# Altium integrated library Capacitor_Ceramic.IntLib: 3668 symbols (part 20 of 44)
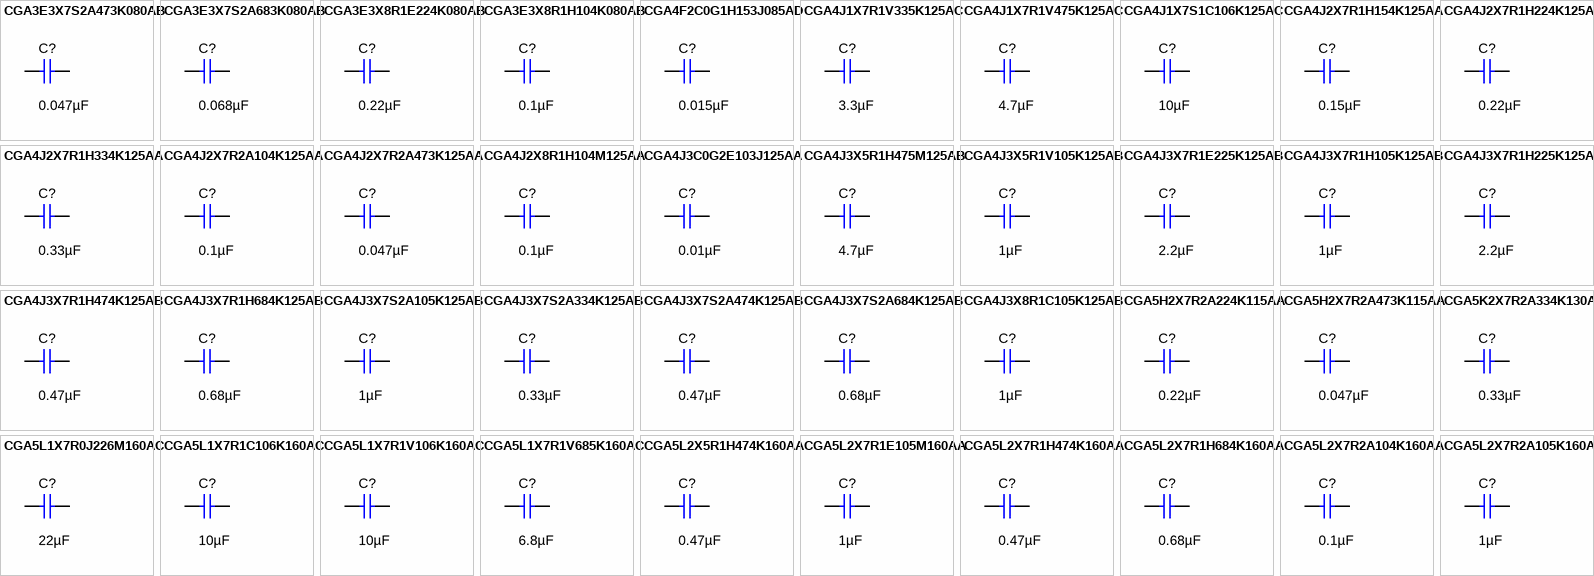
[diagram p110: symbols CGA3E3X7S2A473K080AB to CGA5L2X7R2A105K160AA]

## CGA4J2X7R2A104K125AA
designator C?  ValueDisplayed: 0.1µF  (hidden comment: CGA4J2X7R2A104K125AA)
CAP, CERM, 0.1 µF, 100 V,+/- 10%, X7R, AEC-Q200 Grade 1, 0805; Manufacturer: TDK; Polarized: N; CompType: Capacitor; Value: 0.1uF; U/M: EA; Cap_F: 0.0000001; Tolerance_%: 10; ESR_ohm: 0.020726; Value1: 0.020726 ohm; VDC_V: 100; Value2: 100V; IRMS_A: 1.456; TaMin_C: -55; TaMax_C: 125; Cap_Case: 0805; SizeArea_mm2: 2.5; SizeAreaWB_mm2: 6.75; SizeX_mm: 2; SizeY_mm: 1.25; SizeZ_mm: 1.45; AEC Category: Q200; AEC Qualified: Y; AEC Grade: 1; Green_Lifecycle: Active; Green_REACh: Passed
signal-integrity model Cap
simulation model Cap
footprint 0805_HV
footprint 0805_HV1
footprint 0805
footprint 0805M
footprint 0805L
pins: 1, 2

## CGA4J2X7R2A473K125AA
designator C?  ValueDisplayed: 0.047µF  (hidden comment: CGA4J2X7R2A473K125AA)
CAP, CERM, 0.047 µF, 100 V,+/- 10%, X7R, AEC-Q200 Grade 1, 0805; Manufacturer: TDK; Polarized: N; CompType: Capacitor; Value: 0.047uF; U/M: EA; Cap_F: 0.000000047; Tolerance_%: 10; ESR_ohm: 0.049089; Value1: 0.049089 ohm; VDC_V: 100; Value2: 100V; IRMS_A: 0.963171; TaMin_C: -55; TaMax_C: 125; Cap_Case: 0805; SizeArea_mm2: 2.5; SizeAreaWB_mm2: 6.75; SizeX_mm: 2; SizeY_mm: 1.25; SizeZ_mm: 1.45; AEC Category: Q200; AEC Qualified: Y; AEC Grade: 1
signal-integrity model Cap
simulation model Cap
footprint 0805_HV
footprint 0805_HV1
footprint 0805
footprint 0805M
footprint 0805L
pins: 1, 2

## CGA4J2X8R1H104M125AA
designator C?  ValueDisplayed: 0.1µF  (hidden comment: CGA4J2X8R1H104M125AA)
CAP, CERM, 0.1 µF, 50 V,+/- 20%, X8R, AEC-Q200 Grade 0, 0805; Manufacturer: TDK; Polarized: N; CompType: Capacitor; Value: 0.1uF; U/M: EA; Cap_F: 0.0000001; Tolerance_%: 20; VDC_V: 50; Value2: 50V; TaMin_C: -55; TaMax_C: 150; Cap_Case: 0805; SizeArea_mm2: 2.5; SizeAreaWB_mm2: 6.75; SizeX_mm: 2; SizeY_mm: 1.25; SizeZ_mm: 1.45; AEC Category: Q200; AEC Qualified: Y; AEC Grade: 0
signal-integrity model Cap
simulation model Cap
footprint 0805_HV
footprint 0805_HV1
footprint 0805
footprint 0805M
footprint 0805L
pins: 1, 2

## CGA4J3C0G2E103J125AA
designator C?  ValueDisplayed: 0.01µF  (hidden comment: CGA4J3C0G2E103J125AA)
CAP, CERM, 0.01 µF, 250 V,+/- 5%, C0G/NP0, AEC-Q200 Grade 1, 0805; Manufacturer: TDK; Polarized: N; CompType: Capacitor; Value: 0.01uF; U/M: EA; Cap_F: 0.00000001; Tolerance_%: 5; VDC_V: 250; Value2: 250V; TaMin_C: -55; TaMax_C: 125; Cap_Case: 0805; SizeArea_mm2: 2.5; SizeAreaWB_mm2: 6.75; SizeX_mm: 2; SizeY_mm: 1.25; SizeZ_mm: 1.45; AEC Category: Q200; AEC Qualified: Y; AEC Grade: 1; Green_Lifecycle: Active; Green_REACh: Passed
signal-integrity model Cap
simulation model Cap
footprint 0805_HV
footprint 0805_HV1
footprint 0805
footprint 0805M
footprint 0805L
pins: 1, 2

## CGA4J3X5R1H475M125AB
designator C?  ValueDisplayed: 4.7µF  (hidden comment: CGA4J3X5R1H475M125AB)
CAP, CERM, 4.7 µF, 50 V,+/- 20%, X5R, AEC-Q200 Grade 3, 0805; Manufacturer: TDK; Polarized: N; CompType: Capacitor; Value: 4.7uF; U/M: EA; Cap_F: 0.0000047; Tolerance_%: 20; VDC_V: 50; Value2: 50V; TaMin_C: -55; TaMax_C: 85; Cap_Case: 0805; SizeArea_mm2: 2.5; SizeAreaWB_mm2: 6.75; SizeX_mm: 2; SizeY_mm: 1.25; SizeZ_mm: 1.45; AEC Category: Q200; AEC Qualified: Y; AEC Grade: 3
signal-integrity model Cap
simulation model Cap
footprint 0805_HV
footprint 0805_HV1
footprint 0805
footprint 0805M
footprint 0805L
pins: 1, 2

## CGA4J3X5R1V105K125AB
designator C?  ValueDisplayed: 1µF  (hidden comment: CGA4J3X5R1V105K125AB)
CAP, CERM, 1 µF, 35 V,+/- 10%, X5R, AEC-Q200 Grade 3, 0805; Manufacturer: TDK; Polarized: N; CompType: Capacitor; Value: 1uF; U/M: EA; Cap_F: 0.000001; Tolerance_%: 10; VDC_V: 35; Value2: 35V; TaMin_C: -55; TaMax_C: 85; Cap_Case: 0805; SizeArea_mm2: 2.5; SizeAreaWB_mm2: 6.75; SizeX_mm: 2; SizeY_mm: 1.25; SizeZ_mm: 1.45; AEC Category: Q200; AEC Qualified: Y; AEC Grade: 3
signal-integrity model Cap
simulation model Cap
footprint 0805_HV
footprint 0805_HV1
footprint 0805
footprint 0805M
footprint 0805L
pins: 1, 2

## CGA4J3X7R1E225K125AB
designator C?  ValueDisplayed: 2.2µF  (hidden comment: CGA4J3X7R1E225K125AB)
CAP, CERM, 2.2 µF, 25 V,+/- 10%, X7R, AEC-Q200 Grade 1, 0805; Manufacturer: TDK; Polarized: N; CompType: Capacitor; Value: 2.2uF; U/M: EA; Cap_F: 0.0000022; Tolerance_%: 10; VDC_V: 25; Value2: 25V; TaMin_C: -55; TaMax_C: 125; Cap_Case: 0805; SizeArea_mm2: 2.5; SizeAreaWB_mm2: 6.75; SizeX_mm: 2; SizeY_mm: 1.25; SizeZ_mm: 1.45; AEC Category: Q200; AEC Qualified: Y; AEC Grade: 1; Green_Lifecycle: Active; Green_REACh: Passed
signal-integrity model Cap
simulation model Cap
footprint 0805_HV
footprint 0805_HV1
footprint 0805
footprint 0805M
footprint 0805L
pins: 1, 2

## CGA4J3X7R1H105K125AB
designator C?  ValueDisplayed: 1µF  (hidden comment: CGA4J3X7R1H105K125AB)
CAP, CERM, 1 µF, 50 V,+/- 10%, X7R, AEC-Q200 Grade 1, 0805; Manufacturer: TDK; Polarized: N; CompType: Capacitor; Value: 1uF; U/M: EA; Cap_F: 0.000001; Tolerance_%: 10; ESR_ohm: 0.008782; Value1: 0.008782 ohm; VDC_V: 50; Value2: 50V; IRMS_A: 2.20488; TaMin_C: -55; TaMax_C: 125; Cap_Case: 0805; SizeArea_mm2: 2.5; SizeAreaWB_mm2: 6.75; SizeX_mm: 2; SizeY_mm: 1.25; SizeZ_mm: 1.45; AEC Category: Q200; AEC Qualified: Y; AEC Grade: 1
signal-integrity model Cap
simulation model Cap
footprint 0805_HV
footprint 0805_HV1
footprint 0805
footprint 0805M
footprint 0805L
pins: 1, 2

## CGA4J3X7R1H225K125AB
designator C?  ValueDisplayed: 2.2µF  (hidden comment: CGA4J3X7R1H225K125AB)
CAP, CERM, 2.2 µF, 50 V,+/- 10%, X7R, AEC-Q200 Grade 1, 0805; Manufacturer: TDK; Polarized: N; CompType: Capacitor; Value: 2.2uF; U/M: EA; Cap_F: 0.0000022; Tolerance_%: 10; ESR_ohm: 0.003288; Value1: 0.003288 ohm; VDC_V: 50; Value2: 50V; IRMS_A: 3.60029; TaMin_C: -55; TaMax_C: 125; Cap_Case: 0805; SizeArea_mm2: 2.5; SizeAreaWB_mm2: 6.75; SizeX_mm: 2; SizeY_mm: 1.25; SizeZ_mm: 1.45; AEC Category: Q200; AEC Qualified: Y; AEC Grade: 1
signal-integrity model Cap
simulation model Cap
footprint 0805_HV
footprint 0805_HV1
footprint 0805
footprint 0805M
footprint 0805L
pins: 1, 2

## CGA4J3X7R1H474K125AB
designator C?  ValueDisplayed: 0.47µF  (hidden comment: CGA4J3X7R1H474K125AB)
CAP, CERM, 0.47 µF, 50 V,+/- 10%, X7R, AEC-Q200 Grade 1, 0805; Manufacturer: TDK; Polarized: N; CompType: Capacitor; Value: 0.47uF; U/M: EA; Cap_F: 0.00000047; Tolerance_%: 10; ESR_ohm: 0.022012; Value1: 0.022012 ohm; VDC_V: 50; Value2: 50V; IRMS_A: 1.39566; TaMin_C: -55; TaMax_C: 125; Cap_Case: 0805; SizeArea_mm2: 2.5; SizeAreaWB_mm2: 6.75; SizeX_mm: 2; SizeY_mm: 1.25; SizeZ_mm: 1.45; AEC Category: Q200; AEC Qualified: Y; AEC Grade: 1
signal-integrity model Cap
simulation model Cap
footprint 0805_HV
footprint 0805_HV1
footprint 0805
footprint 0805M
footprint 0805L
pins: 1, 2

## CGA4J3X7R1H684K125AB
designator C?  ValueDisplayed: 0.68µF  (hidden comment: CGA4J3X7R1H684K125AB)
CAP, CERM, 0.68 µF, 50 V,+/- 10%, X7R, AEC-Q200 Grade 1, 0805; Manufacturer: TDK; Polarized: N; CompType: Capacitor; Value: 0.68uF; U/M: EA; Cap_F: 0.00000068; Tolerance_%: 10; ESR_ohm: 0.011711; Value1: 0.011711 ohm; VDC_V: 50; Value2: 50V; IRMS_A: 1.91098; TaMin_C: -55; TaMax_C: 125; Cap_Case: 0805; SizeArea_mm2: 2.5; SizeAreaWB_mm2: 6.75; SizeX_mm: 2; SizeY_mm: 1.25; SizeZ_mm: 1.45; AEC Category: Q200; AEC Qualified: Y; AEC Grade: 1
signal-integrity model Cap
simulation model Cap
footprint 0805_HV
footprint 0805_HV1
footprint 0805
footprint 0805M
footprint 0805L
pins: 1, 2

## CGA4J3X7S2A105K125AB
designator C?  ValueDisplayed: 1µF  (hidden comment: CGA4J3X7S2A105K125AB)
CAP, CERM, 1 µF, 100 V,+/- 10%, X7S, AEC-Q200 Grade 1, 0805; Manufacturer: TDK; Polarized: N; CompType: Capacitor; Value: 1uF; U/M: EA; Cap_F: 0.000001; Tolerance_%: 10; ESR_ohm: 0.008255; Value1: 0.008255 ohm; VDC_V: 100; Value2: 100V; IRMS_A: 2.27442; TaMin_C: -55; TaMax_C: 125; Cap_Case: 0805; SizeArea_mm2: 2.5; SizeAreaWB_mm2: 6.75; SizeX_mm: 2; SizeY_mm: 1.25; SizeZ_mm: 1.45; AEC Category: Q200; AEC Qualified: Y; AEC Grade: 1
signal-integrity model Cap
simulation model Cap
footprint 0805_HV
footprint 0805_HV1
footprint 0805
footprint 0805M
footprint 0805L
pins: 1, 2

## CGA4J3X7S2A334K125AB
designator C?  ValueDisplayed: 0.33µF  (hidden comment: CGA4J3X7S2A334K125AB)
CAP, CERM, 0.33 µF, 100 V,+/- 10%, X7S, AEC-Q200 Grade 1, 0805; Manufacturer: TDK; Polarized: N; CompType: Capacitor; Value: 0.33uF; U/M: EA; Cap_F: 0.00000033; Tolerance_%: 10; ESR_ohm: 0.019477; Value1: 0.019477 ohm; VDC_V: 100; Value2: 100V; IRMS_A: 1.48561; TaMin_C: -55; TaMax_C: 125; Cap_Case: 0805; SizeArea_mm2: 2.5; SizeAreaWB_mm2: 6.75; SizeX_mm: 2; SizeY_mm: 1.25; SizeZ_mm: 1.45; AEC Category: Q200; AEC Qualified: Y; AEC Grade: 1
signal-integrity model Cap
simulation model Cap
footprint 0805_HV
footprint 0805_HV1
footprint 0805
footprint 0805M
footprint 0805L
pins: 1, 2

## CGA4J3X7S2A474K125AB
designator C?  ValueDisplayed: 0.47µF  (hidden comment: CGA4J3X7S2A474K125AB)
CAP, CERM, 0.47 µF, 100 V,+/- 10%, X7S, AEC-Q200 Grade 1, 0805; Manufacturer: TDK; Polarized: N; CompType: Capacitor; Value: 0.47uF; U/M: EA; Cap_F: 0.00000047; Tolerance_%: 10; ESR_ohm: 0.017152; Value1: 0.017152 ohm; VDC_V: 100; Value2: 100V; IRMS_A: 1.58068; TaMin_C: -55; TaMax_C: 125; Cap_Case: 0805; SizeArea_mm2: 2.5; SizeAreaWB_mm2: 6.75; SizeX_mm: 2; SizeY_mm: 1.25; SizeZ_mm: 1.45; AEC Category: Q200; AEC Qualified: Y; AEC Grade: 1
signal-integrity model Cap
simulation model Cap
footprint 0805_HV
footprint 0805_HV1
footprint 0805
footprint 0805M
footprint 0805L
pins: 1, 2

## CGA4J3X7S2A684K125AB
designator C?  ValueDisplayed: 0.68µF  (hidden comment: CGA4J3X7S2A684K125AB)
CAP, CERM, 0.68 µF, 100 V,+/- 10%, X7S, AEC-Q200 Grade 1, 0805; Manufacturer: TDK; Polarized: N; CompType: Capacitor; Value: 0.68uF; U/M: EA; Cap_F: 0.00000068; Tolerance_%: 10; ESR_ohm: 0.009732; Value1: 0.009732 ohm; VDC_V: 100; Value2: 100V; IRMS_A: 2.09614; TaMin_C: -55; TaMax_C: 125; Cap_Case: 0805; SizeArea_mm2: 2.5; SizeAreaWB_mm2: 6.75; SizeX_mm: 2; SizeY_mm: 1.25; SizeZ_mm: 1.45; AEC Category: Q200; AEC Qualified: Y; AEC Grade: 1
signal-integrity model Cap
simulation model Cap
footprint 0805_HV
footprint 0805_HV1
footprint 0805
footprint 0805M
footprint 0805L
pins: 1, 2

## CGA4J3X8R1C105K125AB
designator C?  ValueDisplayed: 1µF  (hidden comment: CGA4J3X8R1C105K125AB)
CAP, CERM, 1 µF, 16 V,+/- 20%, X8R, AEC-Q200 Grade 0, 0805; Manufacturer: TDK; Polarized: N; CompType: Capacitor; Value: 1uF; U/M: EA; Cap_F: 0.000001; Tolerance_%: 20; VDC_V: 16; Value2: 16V; TaMin_C: -55; TaMax_C: 150; Cap_Case: 0805; SizeArea_mm2: 2.5; SizeAreaWB_mm2: 6.75; SizeX_mm: 2; SizeY_mm: 1.25; SizeZ_mm: 1.45; AEC Category: Q200; AEC Qualified: Y; AEC Grade: 0
signal-integrity model Cap
simulation model Cap
footprint 0805_HV
footprint 0805_HV1
footprint 0805
footprint 0805M
footprint 0805L
pins: 1, 2

## CGA5H2X7R2A224K115AA
designator C?  ValueDisplayed: 0.22µF  (hidden comment: CGA5H2X7R2A224K115AA)
CAP, CERM, 0.22 µF, 100 V,+/- 10%, X7R, AEC-Q200 Grade 1, 1206; Manufacturer: TDK; Polarized: N; CompType: Capacitor; Value: 0.22uF; U/M: EA; Cap_F: 0.00000022; Tolerance_%: 10; ESR_ohm: 0.01493; Value1: 0.01493 ohm; VDC_V: 100; Value2: 100V; IRMS_A: 1.89056; TaMin_C: -55; TaMax_C: 125; Cap_Case: 1206; SizeArea_mm2: 5.12; SizeAreaWB_mm2: 10.92; SizeX_mm: 3.2; SizeY_mm: 1.6; SizeZ_mm: 1.35; AEC Category: Q200; AEC Qualified: Y; AEC Grade: 1
signal-integrity model Cap
simulation model Cap
footprint 1206
footprint 1206M
footprint 1206L
pins: 1, 2

## CGA5H2X7R2A473K115AA
designator C?  ValueDisplayed: 0.047µF  (hidden comment: CGA5H2X7R2A473K115AA)
CAP, CERM, 0.047 µF, 100 V,+/- 10%, X7R, AEC-Q200 Grade 1, 1206; Manufacturer: TDK; Polarized: N; CompType: Capacitor; Value: 0.047uF; U/M: EA; Cap_F: 0.000000047; Tolerance_%: 10; ESR_ohm: 0.065629; Value1: 0.065629 ohm; VDC_V: 100; Value2: 100V; IRMS_A: 0.927421; TaMin_C: -55; TaMax_C: 125; Cap_Case: 1206; SizeArea_mm2: 5.12; SizeAreaWB_mm2: 10.92; SizeX_mm: 3.2; SizeY_mm: 1.6; SizeZ_mm: 1.35; AEC Category: Q200; AEC Qualified: Y; AEC Grade: 1
signal-integrity model Cap
simulation model Cap
footprint 1206
footprint 1206M
footprint 1206L
pins: 1, 2

## CGA5K2X7R2A334K130AA
designator C?  ValueDisplayed: 0.33µF  (hidden comment: CGA5K2X7R2A334K130AA)
CAP, CERM, 0.33 µF, 100 V,+/- 10%, X7R, AEC-Q200 Grade 1, 1206; Manufacturer: TDK; Polarized: N; CompType: Capacitor; Value: 0.33uF; U/M: EA; Cap_F: 0.00000033; Tolerance_%: 10; ESR_ohm: 0.011504; Value1: 0.011504 ohm; VDC_V: 100; Value2: 100V; IRMS_A: 2.14919; TaMin_C: -55; TaMax_C: 125; Cap_Case: 1206; SizeArea_mm2: 5.12; SizeAreaWB_mm2: 10.92; SizeX_mm: 3.2; SizeY_mm: 1.6; SizeZ_mm: 1.5; AEC Category: Q200; AEC Qualified: Y; AEC Grade: 1
signal-integrity model Cap
simulation model Cap
footprint 1206_150
footprint 1206_150M
footprint 1206_150L
pins: 1, 2

## CGA5L1X7R0J226M160AC
designator C?  ValueDisplayed: 22µF  (hidden comment: CGA5L1X7R0J226M160AC)
CAP, CERM, 22 µF, 6.3 V,+/- 10%, X7R, AEC-Q200 Grade 1, 1206; Manufacturer: TDK; Polarized: N; CompType: Capacitor; Value: 22uF; U/M: EA; Cap_F: 0.000022; Tolerance_%: 10; ESR_ohm: 0.001872; Value1: 0.001872 ohm; VDC_V: 6.3; Value2: 6.3V; IRMS_A: 5.30203; TaMin_C: -55; TaMax_C: 125; Cap_Case: 1206; SizeArea_mm2: 5.12; SizeAreaWB_mm2: 10.92; SizeX_mm: 3.2; SizeY_mm: 1.6; SizeZ_mm: 1.8; AEC Category: Q200; AEC Qualified: Y; AEC Grade: 1; Green_Lifecycle: Active; Green_REACh: Passed
signal-integrity model Cap
simulation model Cap
footprint 1206_180
footprint 1206_180M
footprint 1206_180L
pins: 1, 2

## CGA5L1X7R1C106K160AC
designator C?  ValueDisplayed: 10µF  (hidden comment: CGA5L1X7R1C106K160AC)
CAP, CERM, 10 µF, 16 V,+/- 10%, X7R, AEC-Q200 Grade 1, 1206; Manufacturer: TDK; Polarized: N; CompType: Capacitor; Value: 10uF; U/M: EA; Cap_F: 0.00001; Tolerance_%: 10; VDC_V: 16; Value2: 16V; TaMin_C: -55; TaMax_C: 125; Cap_Case: 1206; SizeArea_mm2: 5.12; SizeAreaWB_mm2: 10.92; SizeX_mm: 3.2; SizeY_mm: 1.6; SizeZ_mm: 1.9; AEC Category: Q200; AEC Qualified: Y; AEC Grade: 1
signal-integrity model Cap
simulation model Cap
footprint 1206_190
footprint 1206_190M
footprint 1206_190L
pins: 1, 2

## CGA5L1X7R1V106K160AC
designator C?  ValueDisplayed: 10µF  (hidden comment: CGA5L1X7R1V106K160AC)
CAP, CERM, 10 µF, 35 V,+/- 10%, X7R, AEC-Q200 Grade 1, 1206; Manufacturer: TDK; Polarized: N; CompType: Capacitor; Value: 10uF; U/M: EA; Cap_F: 0.00001; Tolerance_%: 10; ESR_ohm: 0.002229; Value1: 0.002229 ohm; VDC_V: 35; Value2: 35V; IRMS_A: 4.85932; TaMin_C: -55; TaMax_C: 125; Cap_Case: 1206; SizeArea_mm2: 5.12; SizeAreaWB_mm2: 10.92; SizeX_mm: 3.2; SizeY_mm: 1.6; SizeZ_mm: 1.9; AEC Category: Q200; AEC Qualified: Y; AEC Grade: 1
signal-integrity model Cap
simulation model Cap
footprint 1206_190
footprint 1206_190M
footprint 1206_190L
pins: 1, 2

## CGA5L1X7R1V685K160AC
designator C?  ValueDisplayed: 6.8µF  (hidden comment: CGA5L1X7R1V685K160AC)
CAP, CERM, 6.8 µF, 35 V,+/- 10%, X7R, AEC-Q200 Grade 1, 1206; Manufacturer: TDK; Polarized: N; CompType: Capacitor; Value: 6.8uF; U/M: EA; Cap_F: 0.0000068; Tolerance_%: 10; ESR_ohm: 0.003202; Value1: 0.003202 ohm; VDC_V: 35; Value2: 35V; IRMS_A: 4.05527; TaMin_C: -55; TaMax_C: 125; Cap_Case: 1206; SizeArea_mm2: 5.12; SizeAreaWB_mm2: 10.92; SizeX_mm: 3.2; SizeY_mm: 1.6; SizeZ_mm: 1.9; AEC Category: Q200; AEC Qualified: Y; AEC Grade: 1
signal-integrity model Cap
simulation model Cap
footprint 1206_190
footprint 1206_190M
footprint 1206_190L
pins: 1, 2

## CGA5L2X5R1H474K160AA
designator C?  ValueDisplayed: 0.47µF  (hidden comment: CGA5L2X5R1H474K160AA)
CAP, CERM, 0.47 µF, 50 V,+/- 10%, X5R, AEC-Q200 Grade 3, 1206; Manufacturer: TDK; Polarized: N; CompType: Capacitor; Value: 0.47uF; U/M: EA; Cap_F: 0.00000047; Tolerance_%: 10; VDC_V: 50; Value2: 50V; TaMin_C: -55; TaMax_C: 85; Cap_Case: 1206; SizeArea_mm2: 5.12; SizeAreaWB_mm2: 10.92; SizeX_mm: 3.2; SizeY_mm: 1.6; SizeZ_mm: 1.9; AEC Category: Q200; AEC Qualified: Y; AEC Grade: 3
signal-integrity model Cap
simulation model Cap
footprint 1206_190
footprint 1206_190M
footprint 1206_190L
pins: 1, 2

## CGA5L2X7R1E105M160AA
designator C?  ValueDisplayed: 1µF  (hidden comment: CGA5L2X7R1E105M160AA)
CAP, CERM, 1 µF, 25 V,+/- 20%, X7R, AEC-Q200 Grade 1, 1206; Manufacturer: TDK; Polarized: N; CompType: Capacitor; Value: 1uF; U/M: EA; Cap_F: 0.000001; Tolerance_%: 20; VDC_V: 25; Value2: 25V; TaMin_C: -55; TaMax_C: 125; Cap_Case: 1206; SizeArea_mm2: 5.12; SizeAreaWB_mm2: 10.92; SizeX_mm: 3.2; SizeY_mm: 1.6; SizeZ_mm: 1.9; AEC Category: Q200; AEC Qualified: Y; AEC Grade: 1
signal-integrity model Cap
simulation model Cap
footprint 1206_190
footprint 1206_190M
footprint 1206_190L
pins: 1, 2

## CGA5L2X7R1H474K160AA
designator C?  ValueDisplayed: 0.47µF  (hidden comment: CGA5L2X7R1H474K160AA)
CAP, CERM, 0.47 µF, 50 V,+/- 10%, X7R, AEC-Q200 Grade 1, 1206; Manufacturer: TDK; Polarized: N; CompType: Capacitor; Value: 0.47uF; U/M: EA; Cap_F: 0.00000047; Tolerance_%: 10; ESR_ohm: 0.009426; Value1: 0.009426 ohm; VDC_V: 50; Value2: 50V; IRMS_A: 2.37046; TaMin_C: -55; TaMax_C: 125; Cap_Case: 1206; SizeArea_mm2: 5.12; SizeAreaWB_mm2: 10.92; SizeX_mm: 3.2; SizeY_mm: 1.6; SizeZ_mm: 1.8; AEC Category: Q200; AEC Qualified: Y; AEC Grade: 1
signal-integrity model Cap
simulation model Cap
footprint 1206_180
footprint 1206_180M
footprint 1206_180L
pins: 1, 2

## CGA5L2X7R1H684K160AA
designator C?  ValueDisplayed: 0.68µF  (hidden comment: CGA5L2X7R1H684K160AA)
CAP, CERM, 0.68 µF, 50 V,+/- 10%, X7R, AEC-Q200 Grade 1, 1206; Manufacturer: TDK; Polarized: N; CompType: Capacitor; Value: 0.68uF; U/M: EA; Cap_F: 0.00000068; Tolerance_%: 10; ESR_ohm: 0.009045; Value1: 0.009045 ohm; VDC_V: 50; Value2: 50V; IRMS_A: 2.41792; TaMin_C: -55; TaMax_C: 125; Cap_Case: 1206; SizeArea_mm2: 5.12; SizeAreaWB_mm2: 10.92; SizeX_mm: 3.2; SizeY_mm: 1.6; SizeZ_mm: 1.8; AEC Category: Q200; AEC Qualified: Y; AEC Grade: 1
signal-integrity model Cap
simulation model Cap
footprint 1206_180
footprint 1206_180M
footprint 1206_180L
pins: 1, 2

## CGA5L2X7R2A104K160AA
designator C?  ValueDisplayed: 0.1µF  (hidden comment: CGA5L2X7R2A104K160AA)
CAP, CERM, 0.1 µF, 100 V,+/- 10%, X7R, AEC-Q200 Grade 1, 1206; Manufacturer: TDK; Polarized: N; CompType: Capacitor; Value: 0.1uF; U/M: EA; Cap_F: 0.0000001; Tolerance_%: 10; ESR_ohm: 0.030343; Value1: 0.030343 ohm; VDC_V: 100; Value2: 100V; IRMS_A: 1.33802; TaMin_C: -55; TaMax_C: 125; Cap_Case: 1206; SizeArea_mm2: 5.12; SizeAreaWB_mm2: 10.92; SizeX_mm: 3.2; SizeY_mm: 1.6; SizeZ_mm: 1.8; AEC Category: Q200; AEC Qualified: Y; AEC Grade: 1; Green_Lifecycle: Active; Green_REACh: Passed
signal-integrity model Cap
simulation model Cap
footprint 1206_180
footprint 1206_180M
footprint 1206_180L
pins: 1, 2

## CGA5L2X7R2A105K160AA
designator C?  ValueDisplayed: 1µF  (hidden comment: CGA5L2X7R2A105K160AA)
CAP, CERM, 1 µF, 100 V,+/- 10%, X7R, AEC-Q200 Grade 1, 1206; Manufacturer: TDK; Polarized: N; CompType: Capacitor; Value: 1uF; U/M: EA; Cap_F: 0.000001; Tolerance_%: 10; ESR_ohm: 0.004575; Value1: 0.004575 ohm; VDC_V: 100; Value2: 100V; IRMS_A: 3.39639; TaMin_C: -55; TaMax_C: 125; Cap_Case: 1206; SizeArea_mm2: 5.12; SizeAreaWB_mm2: 10.92; SizeX_mm: 3.2; SizeY_mm: 1.6; SizeZ_mm: 1.8; AEC Category: Q200; AEC Qualified: Y; AEC Grade: 1
signal-integrity model Cap
simulation model Cap
footprint 1206_180
footprint 1206_180M
footprint 1206_180L
pins: 1, 2

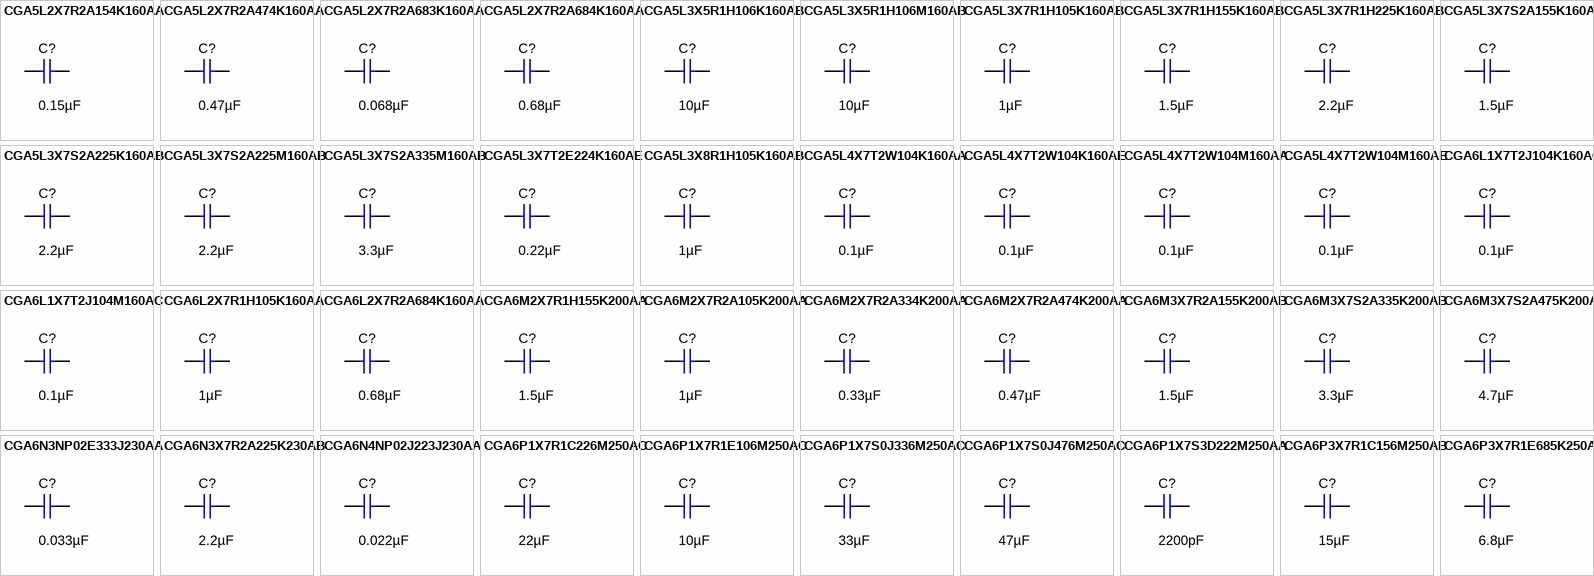
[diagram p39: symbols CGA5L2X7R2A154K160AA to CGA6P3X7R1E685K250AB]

## CGA5L2X7R2A154K160AA
designator C?  ValueDisplayed: 0.15µF  (hidden comment: CGA5L2X7R2A154K160AA)
CAP, CERM, 0.15 µF, 100 V,+/- 10%, X7R, AEC-Q200 Grade 1, 1206; Manufacturer: TDK; Polarized: N; CompType: Capacitor; Value: 0.15uF; U/M: EA; Cap_F: 0.00000015; Tolerance_%: 10; ESR_ohm: 0.021684; Value1: 0.021684 ohm; VDC_V: 100; Value2: 100V; IRMS_A: 1.57495; TaMin_C: -55; TaMax_C: 125; Cap_Case: 1206; SizeArea_mm2: 5.12; SizeAreaWB_mm2: 10.92; SizeX_mm: 3.2; SizeY_mm: 1.6; SizeZ_mm: 1.8; AEC Category: Q200; AEC Qualified: Y; AEC Grade: 1
signal-integrity model Cap
simulation model Cap
footprint 1206_180
footprint 1206_180M
footprint 1206_180L
pins: 1, 2

## CGA5L2X7R2A474K160AA
designator C?  ValueDisplayed: 0.47µF  (hidden comment: CGA5L2X7R2A474K160AA)
CAP, CERM, 0.47 µF, 100 V,+/- 10%, X7R, AEC-Q200 Grade 1, 1206; Manufacturer: TDK; Polarized: N; CompType: Capacitor; Value: 0.47uF; U/M: EA; Cap_F: 0.00000047; Tolerance_%: 10; ESR_ohm: 0.007558; Value1: 0.007558 ohm; VDC_V: 100; Value2: 100V; IRMS_A: 2.64716; TaMin_C: -55; TaMax_C: 125; Cap_Case: 1206; SizeArea_mm2: 5.12; SizeAreaWB_mm2: 10.92; SizeX_mm: 3.2; SizeY_mm: 1.6; SizeZ_mm: 1.8; AEC Category: Q200; AEC Qualified: Y; AEC Grade: 1
signal-integrity model Cap
simulation model Cap
footprint 1206_180
footprint 1206_180M
footprint 1206_180L
pins: 1, 2

## CGA5L2X7R2A683K160AA
designator C?  ValueDisplayed: 0.068µF  (hidden comment: CGA5L2X7R2A683K160AA)
CAP, CERM, 0.068 µF, 100 V,+/- 10%, X7R, AEC-Q200 Grade 1, 1206; Manufacturer: TDK; Polarized: N; CompType: Capacitor; Value: 0.068uF; U/M: EA; Cap_F: 0.000000068; Tolerance_%: 10; ESR_ohm: 0.046525; Value1: 0.046525 ohm; VDC_V: 100; Value2: 100V; IRMS_A: 1.08982; TaMin_C: -55; TaMax_C: 125; Cap_Case: 1206; SizeArea_mm2: 5.12; SizeAreaWB_mm2: 10.92; SizeX_mm: 3.2; SizeY_mm: 1.6; SizeZ_mm: 1.8; AEC Category: Q200; AEC Qualified: Y; AEC Grade: 1
signal-integrity model Cap
simulation model Cap
footprint 1206_180
footprint 1206_180M
footprint 1206_180L
pins: 1, 2

## CGA5L2X7R2A684K160AA
designator C?  ValueDisplayed: 0.68µF  (hidden comment: CGA5L2X7R2A684K160AA)
CAP, CERM, 0.68 µF, 100 V,+/- 10%, X7R, AEC-Q200 Grade 1, 1206; Manufacturer: TDK; Polarized: N; CompType: Capacitor; Value: 0.68uF; U/M: EA; Cap_F: 0.00000068; Tolerance_%: 10; ESR_ohm: 0.007371; Value1: 0.007371 ohm; VDC_V: 100; Value2: 100V; IRMS_A: 2.67843; TaMin_C: -55; TaMax_C: 125; Cap_Case: 1206; SizeArea_mm2: 5.12; SizeAreaWB_mm2: 10.92; SizeX_mm: 3.2; SizeY_mm: 1.6; SizeZ_mm: 1.8; AEC Category: Q200; AEC Qualified: Y; AEC Grade: 1
signal-integrity model Cap
simulation model Cap
footprint 1206_180
footprint 1206_180M
footprint 1206_180L
pins: 1, 2

## CGA5L3X5R1H106K160AB
designator C?  ValueDisplayed: 10µF  (hidden comment: CGA5L3X5R1H106K160AB)
CAP, CERM, 10 µF, 50 V,+/- 10%, X5R, 1206; Manufacturer: TDK; Polarized: N; CompType: Capacitor; Value: 10uF; U/M: EA; Cap_F: 0.00001; Tolerance_%: 10; VDC_V: 50; Value2: 50V; TaMin_C: -55; TaMax_C: 85; Cap_Case: 1206; SizeArea_mm2: 5.12; SizeAreaWB_mm2: 10.92; SizeX_mm: 3.2; SizeY_mm: 1.6; SizeZ_mm: 1.9; AEC Category: Q200; Green_Lifecycle: Active; Green_REACh: Passed
signal-integrity model Cap
simulation model Cap
footprint 1206_190
footprint 1206_190M
footprint 1206_190L
pins: 1, 2

## CGA5L3X5R1H106M160AB
designator C?  ValueDisplayed: 10µF  (hidden comment: CGA5L3X5R1H106M160AB)
CAP, CERM, 10 µF, 50 V,+/- 20%, X5R, AEC-Q200 Grade 3, 1206; Manufacturer: TDK; Polarized: N; CompType: Capacitor; Value: 10uF; U/M: EA; Cap_F: 0.00001; Tolerance_%: 20; VDC_V: 50; Value2: 50V; TaMin_C: -55; TaMax_C: 85; Cap_Case: 1206; SizeArea_mm2: 5.12; SizeAreaWB_mm2: 10.92; SizeX_mm: 3.2; SizeY_mm: 1.6; SizeZ_mm: 1.35; AEC Category: Q200; AEC Qualified: Y; AEC Grade: 3
signal-integrity model Cap
simulation model Cap
footprint 1206
footprint 1206M
footprint 1206L
pins: 1, 2

## CGA5L3X7R1H105K160AB
designator C?  ValueDisplayed: 1µF  (hidden comment: CGA5L3X7R1H105K160AB)
CAP, CERM, 1 µF, 50 V,+/- 10%, X7R, AEC-Q200 Grade 1, 1206; Manufacturer: TDK; Polarized: N; CompType: Capacitor; Value: 1uF; U/M: EA; Cap_F: 0.000001; Tolerance_%: 10; ESR_ohm: 0.009289; Value1: 0.009289 ohm; VDC_V: 50; Value2: 50V; IRMS_A: 2.38446; TaMin_C: -55; TaMax_C: 125; Cap_Case: 1206; SizeArea_mm2: 5.12; SizeAreaWB_mm2: 10.92; SizeX_mm: 3.2; SizeY_mm: 1.6; SizeZ_mm: 1.8; AEC Category: Q200; AEC Qualified: Y; AEC Grade: 1
signal-integrity model Cap
simulation model Cap
footprint 1206_180
footprint 1206_180M
footprint 1206_180L
pins: 1, 2

## CGA5L3X7R1H155K160AB
designator C?  ValueDisplayed: 1.5µF  (hidden comment: CGA5L3X7R1H155K160AB)
CAP, CERM, 1.5 µF, 50 V,+/- 10%, X7R, AEC-Q200 Grade 1, 1206; Manufacturer: TDK; Polarized: N; CompType: Capacitor; Value: 1.5uF; U/M: EA; Cap_F: 0.0000015; Tolerance_%: 10; ESR_ohm: 0.007741; Value1: 0.007741 ohm; VDC_V: 50; Value2: 50V; IRMS_A: 2.61033; TaMin_C: -55; TaMax_C: 125; Cap_Case: 1206; SizeArea_mm2: 5.12; SizeAreaWB_mm2: 10.92; SizeX_mm: 3.2; SizeY_mm: 1.6; SizeZ_mm: 1.8; AEC Category: Q200; AEC Qualified: Y; AEC Grade: 1
signal-integrity model Cap
simulation model Cap
footprint 1206_180
footprint 1206_180M
footprint 1206_180L
pins: 1, 2

## CGA5L3X7R1H225K160AB
designator C?  ValueDisplayed: 2.2µF  (hidden comment: CGA5L3X7R1H225K160AB)
CAP, CERM, 2.2 µF, 50 V,+/- 10%, X7R, AEC-Q200 Grade 1, 1206; Manufacturer: TDK; Polarized: N; CompType: Capacitor; Value: 2.2uF; U/M: EA; Cap_F: 0.0000022; Tolerance_%: 10; ESR_ohm: 0.005887; Value1: 0.005887 ohm; VDC_V: 50; Value2: 50V; IRMS_A: 2.99226; TaMin_C: -55; TaMax_C: 125; Cap_Case: 1206; SizeArea_mm2: 5.12; SizeAreaWB_mm2: 10.92; SizeX_mm: 3.2; SizeY_mm: 1.6; SizeZ_mm: 1.8; AEC Category: Q200; AEC Qualified: Y; AEC Grade: 1
signal-integrity model Cap
simulation model Cap
footprint 1206_180
footprint 1206_180M
footprint 1206_180L
pins: 1, 2

## CGA5L3X7S2A155K160AB
designator C?  ValueDisplayed: 1.5µF  (hidden comment: CGA5L3X7S2A155K160AB)
CAP, CERM, 1.5 µF, 100 V,+/- 10%, X7S, AEC-Q200 Grade 1, 1206; Manufacturer: TDK; Polarized: N; CompType: Capacitor; Value: 1.5uF; U/M: EA; Cap_F: 0.0000015; Tolerance_%: 10; ESR_ohm: 0.006319; Value1: 0.006319 ohm; VDC_V: 100; Value2: 100V; IRMS_A: 2.88897; TaMin_C: -55; TaMax_C: 125; Cap_Case: 1206; SizeArea_mm2: 5.12; SizeAreaWB_mm2: 10.92; SizeX_mm: 3.2; SizeY_mm: 1.6; SizeZ_mm: 1.8; AEC Category: Q200; AEC Qualified: Y; AEC Grade: 1
signal-integrity model Cap
simulation model Cap
footprint 1206_180
footprint 1206_180M
footprint 1206_180L
pins: 1, 2

## CGA5L3X7S2A225K160AB
designator C?  ValueDisplayed: 2.2µF  (hidden comment: CGA5L3X7S2A225K160AB)
CAP, CERM, 2.2 µF, 100 V,+/- 10%, X7S, AEC-Q200 Grade 1, 1206; Manufacturer: TDK; Polarized: N; CompType: Capacitor; Value: 2.2uF; U/M: EA; Cap_F: 0.0000022; Tolerance_%: 10; ESR_ohm: 0.005718; Value1: 0.005718 ohm; VDC_V: 100; Value2: 100V; IRMS_A: 3.03632; TaMin_C: -55; TaMax_C: 125; Cap_Case: 1206; SizeArea_mm2: 5.12; SizeAreaWB_mm2: 10.92; SizeX_mm: 3.2; SizeY_mm: 1.6; SizeZ_mm: 1.8; AEC Category: Q200; AEC Qualified: Y; AEC Grade: 1
signal-integrity model Cap
simulation model Cap
footprint 1206_180
footprint 1206_180M
footprint 1206_180L
pins: 1, 2

## CGA5L3X7S2A225M160AB
designator C?  ValueDisplayed: 2.2µF  (hidden comment: CGA5L3X7S2A225M160AB)
CAP, CERM, 2.2 µF, 100 V,+/- 20%, X7S, AEC-Q200 Grade 1, 1206; Manufacturer: TDK; Polarized: N; CompType: Capacitor; Value: 2.2uF; U/M: EA; Cap_F: 0.0000022; Tolerance_%: 20; VDC_V: 100; Value2: 100V; TaMin_C: -55; TaMax_C: 125; Cap_Case: 1206; SizeArea_mm2: 5.12; SizeAreaWB_mm2: 10.92; SizeX_mm: 3.2; SizeY_mm: 1.6; SizeZ_mm: 1.9; AEC Category: Q200; AEC Qualified: Y; AEC Grade: 1; Green_Lifecycle: Active; Green_REACh: Passed
signal-integrity model Cap
simulation model Cap
footprint 1206_190
footprint 1206_190M
footprint 1206_190L
pins: 1, 2

## CGA5L3X7S2A335M160AB
designator C?  ValueDisplayed: 3.3µF  (hidden comment: CGA5L3X7S2A335M160AB)
CAP, CERM, 3.3 µF, 100 V,+/- 20%, X7S, AEC-Q200 Grade 1, 1206; Manufacturer: TDK; Polarized: N; CompType: Capacitor; Value: 3.3uF; U/M: EA; Cap_F: 0.0000033; Tolerance_%: 20; ESR_ohm: 0.003048; Value1: 0.003048 ohm; VDC_V: 100; Value2: 100V; IRMS_A: 4.15703; TaMin_C: -55; TaMax_C: 125; Cap_Case: 1206; SizeArea_mm2: 5.12; SizeAreaWB_mm2: 10.92; SizeX_mm: 3.2; SizeY_mm: 1.6; SizeZ_mm: 1.9; AEC Category: Q200; AEC Qualified: Y; AEC Grade: 1
signal-integrity model Cap
simulation model Cap
footprint 1206_190
footprint 1206_190M
footprint 1206_190L
pins: 1, 2

## CGA5L3X7T2E224K160AE
designator C?  ValueDisplayed: 0.22µF  (hidden comment: CGA5L3X7T2E224K160AE)
CAP, CERM, 0.22 µF, 250 V,+/- 10%, X7T, AEC-Q200 Grade 1, 1206; Manufacturer: TDK; Polarized: N; CompType: Capacitor; Value: 0.22uF; U/M: EA; Cap_F: 0.00000022; Tolerance_%: 10; VDC_V: 250; Value2: 250V; TaMin_C: -55; TaMax_C: 125; Cap_Case: 1206; SizeArea_mm2: 5.12; SizeAreaWB_mm2: 10.92; SizeX_mm: 3.2; SizeY_mm: 1.6; SizeZ_mm: 1.35; AEC Category: Q200; AEC Qualified: Y; AEC Grade: 1; Green_Lifecycle: Active; Green_REACh: Passed
signal-integrity model Cap
simulation model Cap
footprint 1206
footprint 1206M
footprint 1206L
pins: 1, 2

## CGA5L3X8R1H105K160AB
designator C?  ValueDisplayed: 1µF  (hidden comment: CGA5L3X8R1H105K160AB)
CAP, CERM, 1 µF, 50 V,+/- 10%, X8R, AEC-Q200 Grade 0, 1206; Manufacturer: TDK; Polarized: N; CompType: Capacitor; Value: 1uF; U/M: EA; Cap_F: 0.000001; Tolerance_%: 10; VDC_V: 50; Value2: 50V; TaMin_C: -55; TaMax_C: 150; Cap_Case: 1206; SizeArea_mm2: 5.12; SizeAreaWB_mm2: 10.92; SizeX_mm: 3.2; SizeY_mm: 1.6; SizeZ_mm: 1.8; AEC Category: Q200; AEC Qualified: Y; AEC Grade: 0
signal-integrity model Cap
simulation model Cap
footprint 1206_180
footprint 1206_180M
footprint 1206_180L
pins: 1, 2

## CGA5L4X7T2W104K160AA
designator C?  ValueDisplayed: 0.1µF  (hidden comment: CGA5L4X7T2W104K160AA)
CAP, CERM, 0.1 µF, 450 V,+/- 10%, X7T, AEC-Q200 Grade 1, 1206; Manufacturer: TDK; Polarized: N; CompType: Capacitor; Value: 0.1uF; U/M: EA; Cap_F: 0.0000001; Tolerance_%: 10; VDC_V: 450; Value2: 450V; TaMin_C: -55; TaMax_C: 125; Cap_Case: 1206; SizeArea_mm2: 5.12; SizeAreaWB_mm2: 10.92; SizeX_mm: 3.2; SizeY_mm: 1.6; SizeZ_mm: 1.9; AEC Category: Q200; AEC Qualified: Y; AEC Grade: 1
signal-integrity model Cap
simulation model Cap
footprint 1206_190
footprint 1206_190M
footprint 1206_190L
pins: 1, 2

## CGA5L4X7T2W104K160AE
designator C?  ValueDisplayed: 0.1µF  (hidden comment: CGA5L4X7T2W104K160AE)
CAP, CERM, 0.1 µF, 450 V,+/- 10%, X7T, AEC-Q200 Grade 1, 1206; Manufacturer: TDK; Polarized: N; CompType: Capacitor; Value: 0.1uF; U/M: EA; Cap_F: 0.0000001; Tolerance_%: 10; VDC_V: 450; Value2: 450V; TaMin_C: -55; TaMax_C: 125; Cap_Case: 1206; SizeArea_mm2: 5.12; SizeAreaWB_mm2: 10.92; SizeX_mm: 3.2; SizeY_mm: 1.6; SizeZ_mm: 1.9; AEC Category: Q200; AEC Qualified: Y; AEC Grade: 1
signal-integrity model Cap
simulation model Cap
footprint 1206_190
footprint 1206_190M
footprint 1206_190L
pins: 1, 2

## CGA5L4X7T2W104M160AA
designator C?  ValueDisplayed: 0.1µF  (hidden comment: CGA5L4X7T2W104M160AA)
CAP, CERM, 0.1 µF, 450 V,+/- 20%, X7T, AEC-Q200 Grade 1, 1206; Manufacturer: TDK; Polarized: N; CompType: Capacitor; Value: 0.1uF; U/M: EA; Cap_F: 0.0000001; Tolerance_%: 20; VDC_V: 450; Value2: 450V; TaMin_C: -55; TaMax_C: 125; Cap_Case: 1206; SizeArea_mm2: 5.12; SizeAreaWB_mm2: 10.92; SizeX_mm: 3.2; SizeY_mm: 1.6; SizeZ_mm: 1.8; AEC Category: Q200; AEC Qualified: Y; AEC Grade: 1
signal-integrity model Cap
simulation model Cap
footprint 1206_180
footprint 1206_180M
footprint 1206_180L
pins: 1, 2

## CGA5L4X7T2W104M160AE
designator C?  ValueDisplayed: 0.1µF  (hidden comment: CGA5L4X7T2W104M160AE)
CAP, CERM, 0.1 µF, 450 V,+/- 20%, X7T, AEC-Q200 Grade 1, 1206; Manufacturer: TDK; Polarized: N; CompType: Capacitor; Value: 0.1uF; U/M: EA; Cap_F: 0.0000001; Tolerance_%: 20; VDC_V: 450; Value2: 450V; TaMin_C: -55; TaMax_C: 125; Cap_Case: 1206; SizeArea_mm2: 5.12; SizeAreaWB_mm2: 10.92; SizeX_mm: 3.2; SizeY_mm: 1.6; SizeZ_mm: 1.9; AEC Category: Q200; AEC Qualified: Y; AEC Grade: 1
signal-integrity model Cap
simulation model Cap
footprint 1206_190
footprint 1206_190M
footprint 1206_190L
pins: 1, 2

## CGA6L1X7T2J104K160AC
designator C?  ValueDisplayed: 0.1µF  (hidden comment: CGA6L1X7T2J104K160AC)
CAP, CERM, 0.1 µF, 630 V,+/- 10%, X7R, AEC-Q200 Grade 1, 1210; Manufacturer: TDK; Polarized: N; CompType: Capacitor; Value: 0.1uF; U/M: EA; Cap_F: 0.0000001; Tolerance_%: 10; VDC_V: 630; Value2: 630V; TaMin_C: -55; TaMax_C: 125; Cap_Case: 1210; SizeArea_mm2: 8; SizeAreaWB_mm2: 14.7; SizeX_mm: 3.2; SizeY_mm: 2.5; SizeZ_mm: 2; AEC Category: Q200; AEC Qualified: Y; AEC Grade: 1
signal-integrity model Cap
simulation model Cap
footprint 1210_200
footprint 1210_200M
footprint 1210_200L
pins: 1, 2

## CGA6L1X7T2J104M160AC
designator C?  ValueDisplayed: 0.1µF  (hidden comment: CGA6L1X7T2J104M160AC)
CAP, CERM, 0.1 µF, 630 V,+/- 20%, X7T, AEC-Q200 Grade 1, 1210; Manufacturer: TDK; Polarized: N; CompType: Capacitor; Value: 0.1uF; U/M: EA; Cap_F: 0.0000001; Tolerance_%: 20; VDC_V: 630; Value2: 630V; TaMin_C: -55; TaMax_C: 125; Cap_Case: 1210; SizeArea_mm2: 8; SizeAreaWB_mm2: 14.7; SizeX_mm: 3.2; SizeY_mm: 2.5; SizeZ_mm: 1.8; AEC Category: Q200; AEC Qualified: Y; AEC Grade: 1
signal-integrity model Cap
simulation model Cap
footprint 1210_180
footprint 1210_180M
footprint 1210_180L
pins: 1, 2

## CGA6L2X7R1H105K160AA
designator C?  ValueDisplayed: 1µF  (hidden comment: CGA6L2X7R1H105K160AA)
CAP, CERM, 1 µF, 50 V,+/- 10%, X7R, AEC-Q200 Grade 1, 1210; Manufacturer: TDK; Polarized: N; CompType: Capacitor; Value: 1uF; U/M: EA; Cap_F: 0.000001; Tolerance_%: 10; ESR_ohm: 0.007168; Value1: 0.007168 ohm; VDC_V: 50; Value2: 50V; IRMS_A: 2.75026; TaMin_C: -55; TaMax_C: 125; Cap_Case: 1210; SizeArea_mm2: 8; SizeAreaWB_mm2: 14.7; SizeX_mm: 3.2; SizeY_mm: 2.5; SizeZ_mm: 1.8; AEC Category: Q200; AEC Qualified: Y; AEC Grade: 1
signal-integrity model Cap
simulation model Cap
footprint 1210_180
footprint 1210_180M
footprint 1210_180L
pins: 1, 2

## CGA6L2X7R2A684K160AA
designator C?  ValueDisplayed: 0.68µF  (hidden comment: CGA6L2X7R2A684K160AA)
CAP, CERM, 0.68 µF, 100 V,+/- 10%, X7R, AEC-Q200 Grade 1, 1210; Manufacturer: TDK; Polarized: N; CompType: Capacitor; Value: 0.68uF; U/M: EA; Cap_F: 0.00000068; Tolerance_%: 10; ESR_ohm: 0.005781; Value1: 0.005781 ohm; VDC_V: 100; Value2: 100V; IRMS_A: 3.06493; TaMin_C: -55; TaMax_C: 125; Cap_Case: 1210; SizeArea_mm2: 8; SizeAreaWB_mm2: 14.7; SizeX_mm: 3.2; SizeY_mm: 2.5; SizeZ_mm: 1.8; AEC Category: Q200; AEC Qualified: Y; AEC Grade: 1
signal-integrity model Cap
simulation model Cap
footprint 1210_180
footprint 1210_180M
footprint 1210_180L
pins: 1, 2

## CGA6M2X7R1H155K200AA
designator C?  ValueDisplayed: 1.5µF  (hidden comment: CGA6M2X7R1H155K200AA)
CAP, CERM, 1.5 µF, 50 V,+/- 10%, X7R, AEC-Q200 Grade 1, 1210; Manufacturer: TDK; Polarized: N; CompType: Capacitor; Value: 1.5uF; U/M: EA; Cap_F: 0.0000015; Tolerance_%: 10; ESR_ohm: 0.003947; Value1: 0.003947 ohm; VDC_V: 50; Value2: 50V; IRMS_A: 3.70421; TaMin_C: -55; TaMax_C: 125; Cap_Case: 1210; SizeArea_mm2: 8; SizeAreaWB_mm2: 14.7; SizeX_mm: 3.2; SizeY_mm: 2.5; SizeZ_mm: 2.2; AEC Category: Q200; AEC Qualified: Y; AEC Grade: 1
signal-integrity model Cap
simulation model Cap
footprint 1210_220
footprint 1210_220M
footprint 1210_220L
pins: 1, 2

## CGA6M2X7R2A105K200AA
designator C?  ValueDisplayed: 1µF  (hidden comment: CGA6M2X7R2A105K200AA)
CAP, CERM, 1 µF, 100 V,+/- 10%, X7R, AEC-Q200 Grade 1, 1210; Manufacturer: TDK; Polarized: N; CompType: Capacitor; Value: 1uF; U/M: EA; Cap_F: 0.000001; Tolerance_%: 10; ESR_ohm: 0.004956; Value1: 0.004956 ohm; VDC_V: 100; Value2: 100V; IRMS_A: 3.30731; TaMin_C: -55; TaMax_C: 125; Cap_Case: 1210; SizeArea_mm2: 8; SizeAreaWB_mm2: 14.7; SizeX_mm: 3.2; SizeY_mm: 2.5; SizeZ_mm: 2.2; AEC Category: Q200; AEC Qualified: Y; AEC Grade: 1
signal-integrity model Cap
simulation model Cap
footprint 1210_220
footprint 1210_220M
footprint 1210_220L
pins: 1, 2

## CGA6M2X7R2A334K200AA
designator C?  ValueDisplayed: 0.33µF  (hidden comment: CGA6M2X7R2A334K200AA)
CAP, CERM, 0.33 µF, 100 V,+/- 10%, X7R, AEC-Q200 Grade 1, 1210; Manufacturer: TDK; Polarized: N; CompType: Capacitor; Value: 0.33uF; U/M: EA; Cap_F: 0.00000033; Tolerance_%: 10; ESR_ohm: 0.010566; Value1: 0.010566 ohm; VDC_V: 100; Value2: 100V; IRMS_A: 2.2725; TaMin_C: -55; TaMax_C: 125; Cap_Case: 1210; SizeArea_mm2: 8; SizeAreaWB_mm2: 14.7; SizeX_mm: 3.2; SizeY_mm: 2.5; SizeZ_mm: 2.2; AEC Category: Q200; AEC Qualified: Y; AEC Grade: 1
signal-integrity model Cap
simulation model Cap
footprint 1210_220
footprint 1210_220M
footprint 1210_220L
pins: 1, 2

## CGA6M2X7R2A474K200AA
designator C?  ValueDisplayed: 0.47µF  (hidden comment: CGA6M2X7R2A474K200AA)
CAP, CERM, 0.47 µF, 100 V,+/- 10%, X7R, AEC-Q200 Grade 1, 1210; Manufacturer: TDK; Polarized: N; CompType: Capacitor; Value: 0.47uF; U/M: EA; Cap_F: 0.00000047; Tolerance_%: 10; ESR_ohm: 0.009164; Value1: 0.009164 ohm; VDC_V: 100; Value2: 100V; IRMS_A: 2.43674; TaMin_C: -55; TaMax_C: 125; Cap_Case: 1210; SizeArea_mm2: 8; SizeAreaWB_mm2: 14.7; SizeX_mm: 3.2; SizeY_mm: 2.5; SizeZ_mm: 2.2; AEC Category: Q200; AEC Qualified: Y; AEC Grade: 1
signal-integrity model Cap
simulation model Cap
footprint 1210_220
footprint 1210_220M
footprint 1210_220L
pins: 1, 2

## CGA6M3X7R2A155K200AB
designator C?  ValueDisplayed: 1.5µF  (hidden comment: CGA6M3X7R2A155K200AB)
CAP, CERM, 1.5 µF, 100 V,+/- 10%, X7R, AEC-Q200 Grade 1, 1210; Manufacturer: TDK; Polarized: N; CompType: Capacitor; Value: 1.5uF; U/M: EA; Cap_F: 0.0000015; Tolerance_%: 10; ESR_ohm: 0.003867; Value1: 0.003867 ohm; VDC_V: 100; Value2: 100V; IRMS_A: 3.74252; TaMin_C: -55; TaMax_C: 125; Cap_Case: 1210; SizeArea_mm2: 8; SizeAreaWB_mm2: 14.7; SizeX_mm: 3.2; SizeY_mm: 2.5; SizeZ_mm: 2.2; AEC Category: Q200; AEC Qualified: Y; AEC Grade: 1
signal-integrity model Cap
simulation model Cap
footprint 1210_220
footprint 1210_220M
footprint 1210_220L
pins: 1, 2

## CGA6M3X7S2A335K200AB
designator C?  ValueDisplayed: 3.3µF  (hidden comment: CGA6M3X7S2A335K200AB)
CAP, CERM, 3.3 µF, 100 V,+/- 10%, X7S, AEC-Q200 Grade 1, 1210; Manufacturer: TDK; Polarized: N; CompType: Capacitor; Value: 3.3uF; U/M: EA; Cap_F: 0.0000033; Tolerance_%: 10; ESR_ohm: 0.004682; Value1: 0.004682 ohm; VDC_V: 100; Value2: 100V; IRMS_A: 3.39944; TaMin_C: -55; TaMax_C: 125; Cap_Case: 1210; SizeArea_mm2: 8; SizeAreaWB_mm2: 14.7; SizeX_mm: 3.2; SizeY_mm: 2.5; SizeZ_mm: 2.2; AEC Category: Q200; AEC Qualified: Y; AEC Grade: 1
signal-integrity model Cap
simulation model Cap
footprint 1210_220
footprint 1210_220M
footprint 1210_220L
pins: 1, 2

## CGA6M3X7S2A475K200AB
designator C?  ValueDisplayed: 4.7µF  (hidden comment: CGA6M3X7S2A475K200AB)
CAP, CERM, 4.7 µF, 100 V,+/- 10%, X7S, AEC-Q200 Grade 1, 1210; Manufacturer: TDK; Polarized: N; CompType: Capacitor; Value: 4.7uF; U/M: EA; Cap_F: 0.0000047; Tolerance_%: 10; ESR_ohm: 0.004236; Value1: 0.004236 ohm; VDC_V: 100; Value2: 100V; IRMS_A: 3.57337; TaMin_C: -55; TaMax_C: 125; Cap_Case: 1210; SizeArea_mm2: 8; SizeAreaWB_mm2: 14.7; SizeX_mm: 3.2; SizeY_mm: 2.5; SizeZ_mm: 2.2; AEC Category: Q200; AEC Qualified: Y; AEC Grade: 1
signal-integrity model Cap
simulation model Cap
footprint 1210_220
footprint 1210_220M
footprint 1210_220L
pins: 1, 2

## CGA6N3NP02E333J230AA
designator C?  ValueDisplayed: 0.033µF  (hidden comment: CGA6N3NP02E333J230AA)
CAP, CERM, 0.033 µF, 250 V,+/- 5%, C0G/NP0, AEC-Q200 Grade 0, 1210; Manufacturer: TDK; Polarized: N; CompType: Capacitor; Value: 0.033uF; U/M: EA; Cap_F: 0.000000033; Tolerance_%: 5; VDC_V: 250; Value2: 250V; TaMin_C: -55; TaMax_C: 150; Cap_Case: 1210; SizeArea_mm2: 8; SizeAreaWB_mm2: 14.7; SizeX_mm: 3.2; SizeY_mm: 2.5; SizeZ_mm: 2.8; AEC Category: Q200; AEC Qualified: Y; AEC Grade: 0
signal-integrity model Cap
simulation model Cap
footprint 1210_280
pins: 1, 2

## CGA6N3X7R2A225K230AB
designator C?  ValueDisplayed: 2.2µF  (hidden comment: CGA6N3X7R2A225K230AB)
CAP, CERM, 2.2 µF, 100 V,+/- 10%, X7R, AEC-Q200 Grade 1, 1210; Manufacturer: TDK; Polarized: N; CompType: Capacitor; Value: 2.2uF; U/M: EA; Cap_F: 0.0000022; Tolerance_%: 10; ESR_ohm: 0.00173; Value1: 0.00173 ohm; VDC_V: 100; Value2: 100V; IRMS_A: 5.59317; TaMin_C: -55; TaMax_C: 125; Cap_Case: 1210; SizeArea_mm2: 8; SizeAreaWB_mm2: 14.7; SizeX_mm: 3.2; SizeY_mm: 2.5; AEC Category: Q200; AEC Qualified: Y; AEC Grade: 1
signal-integrity model Cap
simulation model Cap
footprint 1210_250
footprint 1210_250M
footprint 1210_250L
pins: 1, 2

## CGA6N4NP02J223J230AA
designator C?  ValueDisplayed: 0.022µF  (hidden comment: CGA6N4NP02J223J230AA)
CAP, CERM, 0.022 µF, 630 V,+/- 5%, C0G/NP0, AEC-Q200 Grade 0, 1210; Manufacturer: TDK; Polarized: N; CompType: Capacitor; Value: 0.022uF; U/M: EA; Cap_F: 0.000000022; Tolerance_%: 5; VDC_V: 630; Value2: 630V; TaMin_C: -55; TaMax_C: 150; Cap_Case: 1210; SizeArea_mm2: 8; SizeAreaWB_mm2: 14.7; SizeX_mm: 3.2; SizeY_mm: 2.5; AEC Category: Q200; AEC Qualified: Y; AEC Grade: 0
signal-integrity model Cap
simulation model Cap
footprint 1210_250
footprint 1210_250M
footprint 1210_250L
pins: 1, 2

## CGA6P1X7R1C226M250AC
designator C?  ValueDisplayed: 22µF  (hidden comment: CGA6P1X7R1C226M250AC)
CAP, CERM, 22 µF, 16 V,+/- 20%, X7R, AEC-Q200 Grade 1, 1210; Manufacturer: TDK; Polarized: N; CompType: Capacitor; Value: 22uF; U/M: EA; Cap_F: 0.000022; Tolerance_%: 20; ESR_ohm: 0.002582; Value1: 0.002582 ohm; VDC_V: 16; Value2: 16V; IRMS_A: 4.57562; TaMin_C: -55; TaMax_C: 125; Cap_Case: 1210; SizeArea_mm2: 8; SizeAreaWB_mm2: 14.7; SizeX_mm: 3.2; SizeY_mm: 2.5; SizeZ_mm: 2.8; AEC Category: Q200; AEC Qualified: Y; AEC Grade: 1; Green_Lifecycle: Active; Green_REACh: Passed
signal-integrity model Cap
simulation model Cap
footprint 1210_280
pins: 1, 2

## CGA6P1X7R1E106M250AC
designator C?  ValueDisplayed: 10µF  (hidden comment: CGA6P1X7R1E106M250AC)
CAP, CERM, 10 µF, 25 V,+/- 20%, X7R, AEC-Q200 Grade 1, 1210; Manufacturer: TDK; Polarized: N; CompType: Capacitor; Value: 10uF; U/M: EA; Cap_F: 0.00001; Tolerance_%: 20; VDC_V: 25; Value2: 25V; TaMin_C: -55; TaMax_C: 125; Cap_Case: 1210; SizeArea_mm2: 8; SizeAreaWB_mm2: 14.7; SizeX_mm: 3.2; SizeY_mm: 2.5; SizeZ_mm: 2.8; AEC Category: Q200; AEC Qualified: Y; AEC Grade: 1; Green_Lifecycle: Active; Green_REACh: Passed
signal-integrity model Cap
simulation model Cap
footprint 1210_280
pins: 1, 2

## CGA6P1X7S0J336M250AC
designator C?  ValueDisplayed: 33µF  (hidden comment: CGA6P1X7S0J336M250AC)
CAP, CERM, 33 µF, 6.3 V,+/- 20%, X7S, AEC-Q200 Grade 1, 1210; Manufacturer: TDK; Polarized: N; CompType: Capacitor; Value: 33uF; U/M: EA; Cap_F: 0.000033; Tolerance_%: 20; ESR_ohm: 0.002818; Value1: 0.002818 ohm; VDC_V: 6.3; Value2: 6.3V; IRMS_A: 4.3802; TaMin_C: -55; TaMax_C: 125; Cap_Case: 1210; SizeArea_mm2: 8; SizeAreaWB_mm2: 14.7; SizeX_mm: 3.2; SizeY_mm: 2.5; SizeZ_mm: 2.8; AEC Category: Q200; AEC Qualified: Y; AEC Grade: 1
signal-integrity model Cap
simulation model Cap
footprint 1210_280
pins: 1, 2

## CGA6P1X7S0J476M250AC
designator C?  ValueDisplayed: 47µF  (hidden comment: CGA6P1X7S0J476M250AC)
CAP, CERM, 47 µF, 6.3 V,+/- 20%, X7S, AEC-Q200 Grade 1, 1210; Manufacturer: TDK; Polarized: N; CompType: Capacitor; Value: 47uF; U/M: EA; Cap_F: 0.000047; Tolerance_%: 20; ESR_ohm: 0.003602; Value1: 0.003602 ohm; VDC_V: 6.3; Value2: 6.3V; IRMS_A: 3.87414; TaMin_C: -55; TaMax_C: 125; Cap_Case: 1210; SizeArea_mm2: 8; SizeAreaWB_mm2: 14.7; SizeX_mm: 3.2; SizeY_mm: 2.5; SizeZ_mm: 2.8; AEC Category: Q200; AEC Qualified: Y; AEC Grade: 1
signal-integrity model Cap
simulation model Cap
footprint 1210_280
pins: 1, 2

## CGA6P1X7S3D222M250AA
designator C?  ValueDisplayed: 2200pF  (hidden comment: CGA6P1X7S3D222M250AA)
CAP, CERM, 2200 pF, 2000 V,+/- 20%, X7S, AEC-Q200 Grade 1, 1210; Manufacturer: TDK; Polarized: N; CompType: Capacitor; Value: 2200pF; U/M: EA; Cap_F: 0.0000000022; Tolerance_%: 20; VDC_V: 2000; Value2: 2000V; TaMin_C: -55; TaMax_C: 125; Cap_Case: 1210; SizeArea_mm2: 8; SizeAreaWB_mm2: 14.7; SizeX_mm: 3.2; SizeY_mm: 2.5; SizeZ_mm: 2.8; AEC Category: Q200; AEC Qualified: Y; AEC Grade: 1
signal-integrity model Cap
simulation model Cap
footprint 1210_280
pins: 1, 2

## CGA6P3X7R1C156M250AB
designator C?  ValueDisplayed: 15µF  (hidden comment: CGA6P3X7R1C156M250AB)
CAP, CERM, 15 µF, 16 V,+/- 20%, X7R, AEC-Q200 Grade 1, 1210; Manufacturer: TDK; Polarized: N; CompType: Capacitor; Value: 15uF; U/M: EA; Cap_F: 0.000015; Tolerance_%: 20; ESR_ohm: 0.002949; Value1: 0.002949 ohm; VDC_V: 16; Value2: 16V; IRMS_A: 4.28133; TaMin_C: -55; TaMax_C: 125; Cap_Case: 1210; SizeArea_mm2: 8; SizeAreaWB_mm2: 14.7; SizeX_mm: 3.2; SizeY_mm: 2.5; SizeZ_mm: 2.8; AEC Category: Q200; AEC Qualified: Y; AEC Grade: 1
signal-integrity model Cap
simulation model Cap
footprint 1210_280
pins: 1, 2

## CGA6P3X7R1E685K250AB
designator C?  ValueDisplayed: 6.8µF  (hidden comment: CGA6P3X7R1E685K250AB)
CAP, CERM, 6.8 µF, 25 V,+/- 10%, X7R, AEC-Q200 Grade 1, 1210; Manufacturer: TDK; Polarized: N; CompType: Capacitor; Value: 6.8uF; U/M: EA; Cap_F: 0.0000068; Tolerance_%: 10; ESR_ohm: 0.004043; Value1: 0.004043 ohm; VDC_V: 25; Value2: 25V; IRMS_A: 3.65691; TaMin_C: -55; TaMax_C: 125; Cap_Case: 1210; SizeArea_mm2: 8; SizeAreaWB_mm2: 14.7; SizeX_mm: 3.2; SizeY_mm: 2.5; SizeZ_mm: 2.8; AEC Category: Q200; AEC Qualified: Y; AEC Grade: 1
signal-integrity model Cap
simulation model Cap
footprint 1210_280
pins: 1, 2

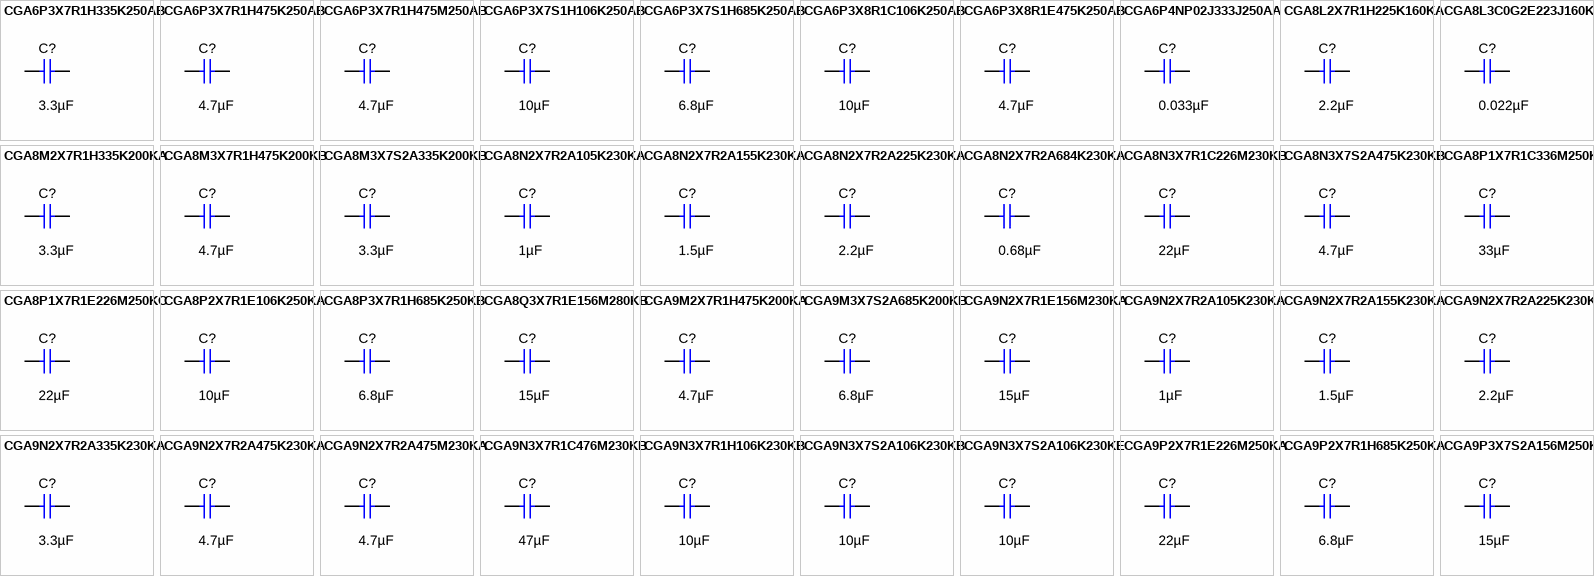
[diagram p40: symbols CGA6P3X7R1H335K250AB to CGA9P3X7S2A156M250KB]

## CGA6P3X7R1H335K250AB
designator C?  ValueDisplayed: 3.3µF  (hidden comment: CGA6P3X7R1H335K250AB)
CAP, CERM, 3.3 µF, 50 V,+/- 10%, X7R, AEC-Q200 Grade 1, 1210; Manufacturer: TDK; Polarized: N; CompType: Capacitor; Value: 3.3uF; U/M: EA; Cap_F: 0.0000033; Tolerance_%: 10; ESR_ohm: 0.003158; Value1: 0.003158 ohm; VDC_V: 50; Value2: 50V; IRMS_A: 4.13891; TaMin_C: -55; TaMax_C: 125; Cap_Case: 1210; SizeArea_mm2: 8; SizeAreaWB_mm2: 14.7; SizeX_mm: 3.2; SizeY_mm: 2.5; SizeZ_mm: 2.8; AEC Category: Q200; AEC Qualified: Y; AEC Grade: 1
signal-integrity model Cap
simulation model Cap
footprint 1210_280
pins: 1, 2

## CGA6P3X7R1H475K250AB
designator C?  ValueDisplayed: 4.7µF  (hidden comment: CGA6P3X7R1H475K250AB)
CAP, CERM, 4.7 µF, 50 V,+/- 10%, X7R, AEC-Q200 Grade 1, 1210; Manufacturer: TDK; Polarized: N; CompType: Capacitor; Value: 4.7uF; U/M: EA; Cap_F: 0.0000047; Tolerance_%: 10; ESR_ohm: 0.003166; Value1: 0.003166 ohm; VDC_V: 50; Value2: 50V; IRMS_A: 4.13311; TaMin_C: -55; TaMax_C: 125; Cap_Case: 1210; SizeArea_mm2: 8; SizeAreaWB_mm2: 14.7; SizeX_mm: 3.2; SizeY_mm: 2.5; SizeZ_mm: 2.8; AEC Category: Q200; AEC Qualified: Y; AEC Grade: 1
signal-integrity model Cap
simulation model Cap
footprint 1210_280
pins: 1, 2

## CGA6P3X7R1H475M250AB
designator C?  ValueDisplayed: 4.7µF  (hidden comment: CGA6P3X7R1H475M250AB)
CAP, CERM, 4.7 µF, 50 V,+/- 20%, X7R, AEC-Q200 Grade 1, 1210; Manufacturer: TDK; Polarized: N; CompType: Capacitor; Value: 4.7uF; U/M: EA; Cap_F: 0.0000047; Tolerance_%: 20; VDC_V: 50; Value2: 50V; TaMin_C: -55; TaMax_C: 125; Cap_Case: 1210; SizeArea_mm2: 8; SizeAreaWB_mm2: 14.7; SizeX_mm: 3.2; SizeY_mm: 2.5; SizeZ_mm: 2.8; AEC Category: Q200; AEC Qualified: Y; AEC Grade: 1; Green_Lifecycle: Active; Green_REACh: Passed
signal-integrity model Cap
simulation model Cap
footprint 1210_280
pins: 1, 2

## CGA6P3X7S1H106K250AB
designator C?  ValueDisplayed: 10µF  (hidden comment: CGA6P3X7S1H106K250AB)
CAP, CERM, 10 µF, 50 V,+/- 10%, X7S, AEC-Q200 Grade 1, 1210; Manufacturer: TDK; Polarized: N; CompType: Capacitor; Value: 10uF; U/M: EA; Cap_F: 0.00001; Tolerance_%: 10; ESR_ohm: 0.002827; Value1: 0.002827 ohm; VDC_V: 50; Value2: 50V; IRMS_A: 4.37286; TaMin_C: -55; TaMax_C: 125; Cap_Case: 1210; SizeArea_mm2: 8; SizeAreaWB_mm2: 14.7; SizeX_mm: 3.2; SizeY_mm: 2.5; SizeZ_mm: 2.8; AEC Category: Q200; AEC Qualified: Y; AEC Grade: 1
signal-integrity model Cap
simulation model Cap
footprint 1210_280
pins: 1, 2

## CGA6P3X7S1H685K250AB
designator C?  ValueDisplayed: 6.8µF  (hidden comment: CGA6P3X7S1H685K250AB)
CAP, CERM, 6.8 µF, 50 V,+/- 10%, X7S, AEC-Q200 Grade 1, 1210; Manufacturer: TDK; Polarized: N; CompType: Capacitor; Value: 6.8uF; U/M: EA; Cap_F: 0.0000068; Tolerance_%: 10; ESR_ohm: 0.002885; Value1: 0.002885 ohm; VDC_V: 50; Value2: 50V; IRMS_A: 4.32962; TaMin_C: -55; TaMax_C: 125; Cap_Case: 1210; SizeArea_mm2: 8; SizeAreaWB_mm2: 14.7; SizeX_mm: 3.2; SizeY_mm: 2.5; SizeZ_mm: 2.8; AEC Category: Q200; AEC Qualified: Y; AEC Grade: 1
signal-integrity model Cap
simulation model Cap
footprint 1210_280
pins: 1, 2

## CGA6P3X8R1C106K250AB
designator C?  ValueDisplayed: 10µF  (hidden comment: CGA6P3X8R1C106K250AB)
CAP, CERM, 10 µF, 16 V,+/- 10%, X8R, AEC-Q200 Grade 0, 1210; Manufacturer: TDK; Polarized: N; CompType: Capacitor; Value: 10uF; U/M: EA; Cap_F: 0.00001; Tolerance_%: 10; VDC_V: 16; Value2: 16V; TaMin_C: -55; TaMax_C: 150; Cap_Case: 1210; SizeArea_mm2: 8; SizeAreaWB_mm2: 14.7; SizeX_mm: 3.2; SizeY_mm: 2.5; SizeZ_mm: 2.8; AEC Category: Q200; AEC Qualified: Y; AEC Grade: 0
signal-integrity model Cap
simulation model Cap
footprint 1210_280
pins: 1, 2

## CGA6P3X8R1E475K250AB
designator C?  ValueDisplayed: 4.7µF  (hidden comment: CGA6P3X8R1E475K250AB)
CAP, CERM, 4.7 µF, 25 V,+/- 10%, X8R, AEC-Q200 Grade 0, 1210; Manufacturer: TDK; Polarized: N; CompType: Capacitor; Value: 4.7uF; U/M: EA; Cap_F: 0.0000047; Tolerance_%: 10; VDC_V: 25; Value2: 25V; TaMin_C: -55; TaMax_C: 150; Cap_Case: 1210; SizeArea_mm2: 8; SizeAreaWB_mm2: 14.7; SizeX_mm: 3.2; SizeY_mm: 2.5; SizeZ_mm: 2.8; AEC Category: Q200; AEC Qualified: Y; AEC Grade: 0
signal-integrity model Cap
simulation model Cap
footprint 1210_280
pins: 1, 2

## CGA6P4NP02J333J250AA
designator C?  ValueDisplayed: 0.033µF  (hidden comment: CGA6P4NP02J333J250AA)
CAP, CERM, 0.033 µF, 630 V,+/- 5%, C0G/NP0, AEC-Q200 Grade 0, 1210; Manufacturer: TDK; Polarized: N; CompType: Capacitor; Value: 0.033uF; U/M: EA; Cap_F: 0.000000033; Tolerance_%: 5; VDC_V: 630; Value2: 630V; TaMin_C: -55; TaMax_C: 150; Cap_Case: 1210; SizeArea_mm2: 8; SizeAreaWB_mm2: 14.7; SizeX_mm: 3.2; SizeY_mm: 2.5; SizeZ_mm: 2.8; AEC Category: Q200; AEC Qualified: Y; AEC Grade: 0
signal-integrity model Cap
simulation model Cap
footprint 1210_280
pins: 1, 2

## CGA8L2X7R1H225K160KA
designator C?  ValueDisplayed: 2.2µF  (hidden comment: CGA8L2X7R1H225K160KA)
CAP, CERM, 2.2 µF, 50 V,+/- 10%, X7R, AEC-Q200 Grade 1, 1812; Manufacturer: TDK; Polarized: N; CompType: Capacitor; Value: 2.2uF; U/M: EA; Cap_F: 0.0000022; Tolerance_%: 10; ESR_ohm: 0.00496; Value1: 0.00496 ohm; VDC_V: 50; Value2: 50V; IRMS_A: 3.44575; TaMin_C: -55; TaMax_C: 125; Cap_Case: 1812; SizeArea_mm2: 14.4; SizeAreaWB_mm2: 23.1; SizeX_mm: 4.5; SizeY_mm: 3.2; SizeZ_mm: 1.8; AEC Category: Q200; AEC Qualified: Y; AEC Grade: 1
signal-integrity model Cap
simulation model Cap
footprint 1812_180
pins: 1, 2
